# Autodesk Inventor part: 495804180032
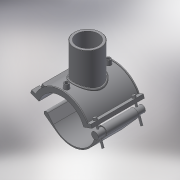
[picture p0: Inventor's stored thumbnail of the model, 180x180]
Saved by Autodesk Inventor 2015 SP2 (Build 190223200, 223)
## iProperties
Created: 2017-07
Part Number: 495804180032
Material: Generic
Description: PLASSON BRANCH SADDLE 180-32
Document SubType Name: Modeling
Designer: KIM
Density: 1 g/cm^3
Appearance: Default
Author: KIM
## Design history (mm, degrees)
derived "495804.ipt"
feature "Solid1::495804.ipt"
feature "Solid2::495804.ipt"
tag "TaggingFeature1"
body "Solid1"
body "Solid2"
other parameters: "B_" = 219, "H_" = 59, "L_" = 118, "d_t" = 6, "d_1" = 32, "H_1" = 49, "d148" = 4.5, "d160" = 4.5, "d2" = 219, "d3" = 45, "d4" = 118, "d5" = 0, "d6" = 0.1, "d8" = 0, "d19" = 6, "d20" = 6, "d21" = 70.8, "d23" = 0, "d24" = 35.4, "d26" = 0, "d27" = 3, "d28" = 3, "d29" = 3, "d31" = 6, "d32" = 0, "d33" = 0, "d34" = 0.6, "d40" = 104, "d41" = 35.2, "d43" = 0, "d45" = 0, "d47" = 159, "d48" = 32, "d50" = 0, "d70" = 15, "d72" = 0, "d73" = 6, "d75" = 5, "d76" = 0, "d77" = 9, "d79" = 15, "d80" = 47.2, "d82" = 5 deg, "d84" = 4, "d85" = 14, "d86" = 0, "d87" = 3, "d88" = 0, "d89" = 1, "d90" = 1, "d91" = 94.4, "d92" = 0, "d93" = 0.5, "d94" = 94.73684, "d96" = 204, "d97" = 2.36, "d98" = 0, "d102" = 0.96, "d103" = 25.6, "d105" = 0, "d109" = -19.66667, "d117" = 0.32, "d120" = 140 deg, "d121" = 24.228, "d122" = 20 deg, "d126" = 0, "d143" = 189, "d150" = 32.4, "d159" = 4, "d161" = 4.5, "d162" = 70.8, "d163" = 0, "d167" = 36, "d168" = 90.90909, "d173" = 1, "d176" = 20 deg, "d177" = 12.6, "d180" = 0, "d185" = 38.35, "d186" = 38.35, "d188" = 6, "d189" = 12.6, "d190" = 0, "d202" = 0, "d216" = 106.2, "d217" = 0, "d221" = 43.66, "d222" = 12.6, "d223" = 7.56, "d225" = 7.56, "d227" = 25.92, "d230" = 111.6, "d236" = 20 deg, "d237" = 107, "d238" = 20 deg, "d239" = 12.6
